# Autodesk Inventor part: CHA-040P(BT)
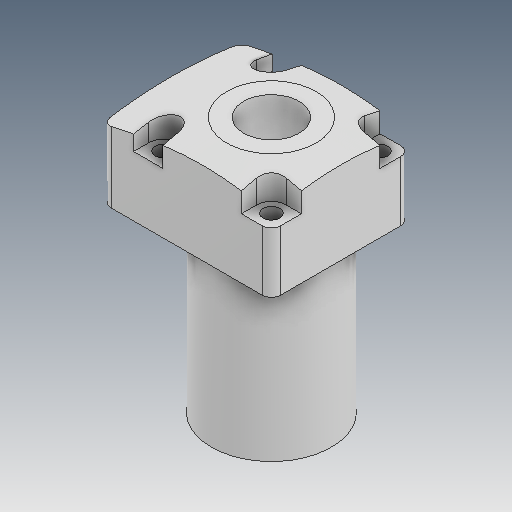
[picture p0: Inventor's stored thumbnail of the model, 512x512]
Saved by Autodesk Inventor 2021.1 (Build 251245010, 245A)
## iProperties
Created: 2021-05
Part Number: CHA-040P(BT)
Material: Ogólny
Document SubType Name: Modeling
Designer: user
Density: 1 g/cm^3
Appearance: Domyślna
Author: user
Revision Number: ÈÎºÎ
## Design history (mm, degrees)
feature "ÇÐ³ý-À­Éì6"
node "Bryła1"
